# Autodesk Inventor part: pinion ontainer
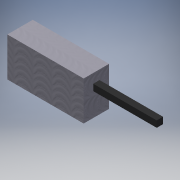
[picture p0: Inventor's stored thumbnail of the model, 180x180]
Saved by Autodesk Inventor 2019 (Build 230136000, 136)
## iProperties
Created: 2021-07
Part Number: pinion ontainer
Material: Aluminum 6061, Welded
Document SubType Name: Modeling
Designer: Avinash
Density: 2.7 g/cm^3
Appearance: Weld - Aluminum
Author: Avinash
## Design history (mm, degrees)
sketch "Sketch1"
  geometry: L1 (0, 0)-(-30, 0); L2 (-30, 0)-(-30, 88); L3 (-30, 88)-(0, 88); L4 (0, 88)-(0, 0); L5 (0, 0)-(40, 0); L6 (40, 0)-(40, 88); L7 (40, 88)-(0, 88); L8 (0, 88)-(0, 0); L9 (40, 0)-(90, 0); L10 (90, 0)-(90, 88); L11 (90, 88)-(40, 88); L12 (40, 88)-(40, 0); L13 (90, 88)-(150, 88); L14 (150, 88)-(150, 0); L15 (150, 0)-(90, 0); L16 (90, 0)-(90, 88)
  constraints: 32 end point, 8 parallel, 4 horizontal, 4 perpendicular
  dimensions: "d0" = 88 distance of L3.end L1.start; "d1" = 30 distance of L2.end L3.end; "d2" = 40 distance of L6.end L7.end; "d3" = 50 distance of L10.end L11.end; "d4" = 60 distance of L14.end L15.end; "d25" = 88 distance between parallel lines of L5 L7; "d26" = 88 distance between parallel lines of L13 L15
extrude "Extrusion1" new body sketch "Sketch1" distance "d5" = 60; taper "d6" = 0 deg
shell "Shell1" dims "d8" = 2
extrude "Extrusion2" join sketch "Sketch1" distance "d9" = 60; taper "d10" = 0 deg
shell "Shell2" dims "d11" = 2
extrude "Extrusion3" join sketch "Sketch1" distance "d12" = 60; taper "d13" = 0 deg
shell "Shell3" dims "d14" = 2
extrude "Extrusion4" join sketch "Sketch1" distance "d15" = 60; taper "d16" = 0 deg
shell "Shell4" dims "d17" = 2
sketch "Sketch2"
  geometry: L1 (-37.5, 53)-(-22.5, 53); L2 (-22.5, 53)-(-22.5, 68); L3 (-22.5, 68)-(-37.5, 68); L4 (-37.5, 68)-(-37.5, 53); L5 (0, 0)-(-60, 0) reference; L6 (-60, 0)-(-60, 88) reference; L7 (0, 88)-(-60, 88) reference
  constraints: 8 end point, 2 parallel, 1 horizontal, 1 perpendicular
  dimensions: "d19" = 15 distance of L1.end L2.end; "d20" = 15 distance of L1.start L1.end; "d21" = 22.5 distance between parallel lines of L6 L4; "d31" = 20 distance between parallel lines of L7 L3
extrude "Extrusion5" join sketch "Sketch2" distance "d22" = 150; taper "d23" = 0 deg
sketch "Sketch3"
  geometry: L1 (0, 0)-(180, 0) reference; L2 (0, 60)-(180, 60) reference; L3 (180, 0)-(0, 0); L4 (0, 0)-(0, 60); L5 (0, 60)-(180, 60); L6 (180, 60)-(180, 0); 1 further point
  constraints: 8 end point, 2 parallel, 1 horizontal, 1 perpendicular
extrude "Extrusion6" join sketch "Sketch3" distance "d27" = 2; taper "d28" = 0 deg
sketch "Sketch4"
  geometry: L1 (178, 58)-(120, 58) reference; L2 (178, 58)-(120, 58); L3 (120, 58)-(120, 2); L4 (120, 2)-(178, 2); L5 (178, 2)-(178, 58); L6 (70, 58)-(118, 58) reference; L7 (68, 2)-(68, 58) reference; L8 (118, 58)-(68, 58); L9 (68, 58)-(68, 2); L10 (68, 2)-(118, 2); L11 (118, 2)-(118, 58); L12 (30, 58)-(68, 58) reference; L13 (30, 2)-(68, 2) reference; L14 (65.844, 58)-(30, 58); L15 (30, 58)-(30, 2); L16 (30, 2)-(65.844, 2); L17 (65.844, 2)-(65.844, 58); L18 (2, 58)-(28, 58) reference; L19 (2, 2)-(28, 2) reference; L20 (2, 58)-(28, 58); L21 (28, 58)-(28, 2); L22 (28, 2)-(2, 2); L23 (2, 2)-(2, 58); 1 further point
  constraints: 32 end point, 8 parallel, 4 horizontal, 4 perpendicular, 1 point on line
extrude "Extrusion7" cut sketch "Sketch4" distance "d29" = 2; taper "d30" = 0 deg
body "Solid1"
